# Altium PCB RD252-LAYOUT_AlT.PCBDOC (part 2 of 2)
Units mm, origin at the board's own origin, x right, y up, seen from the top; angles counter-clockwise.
Board outline 55 x 54 mm, 2 copper layers (TOP, BOTTOM), stack 0 mm thick; 81 components, 42 nets, 652 pads, 0 vias.
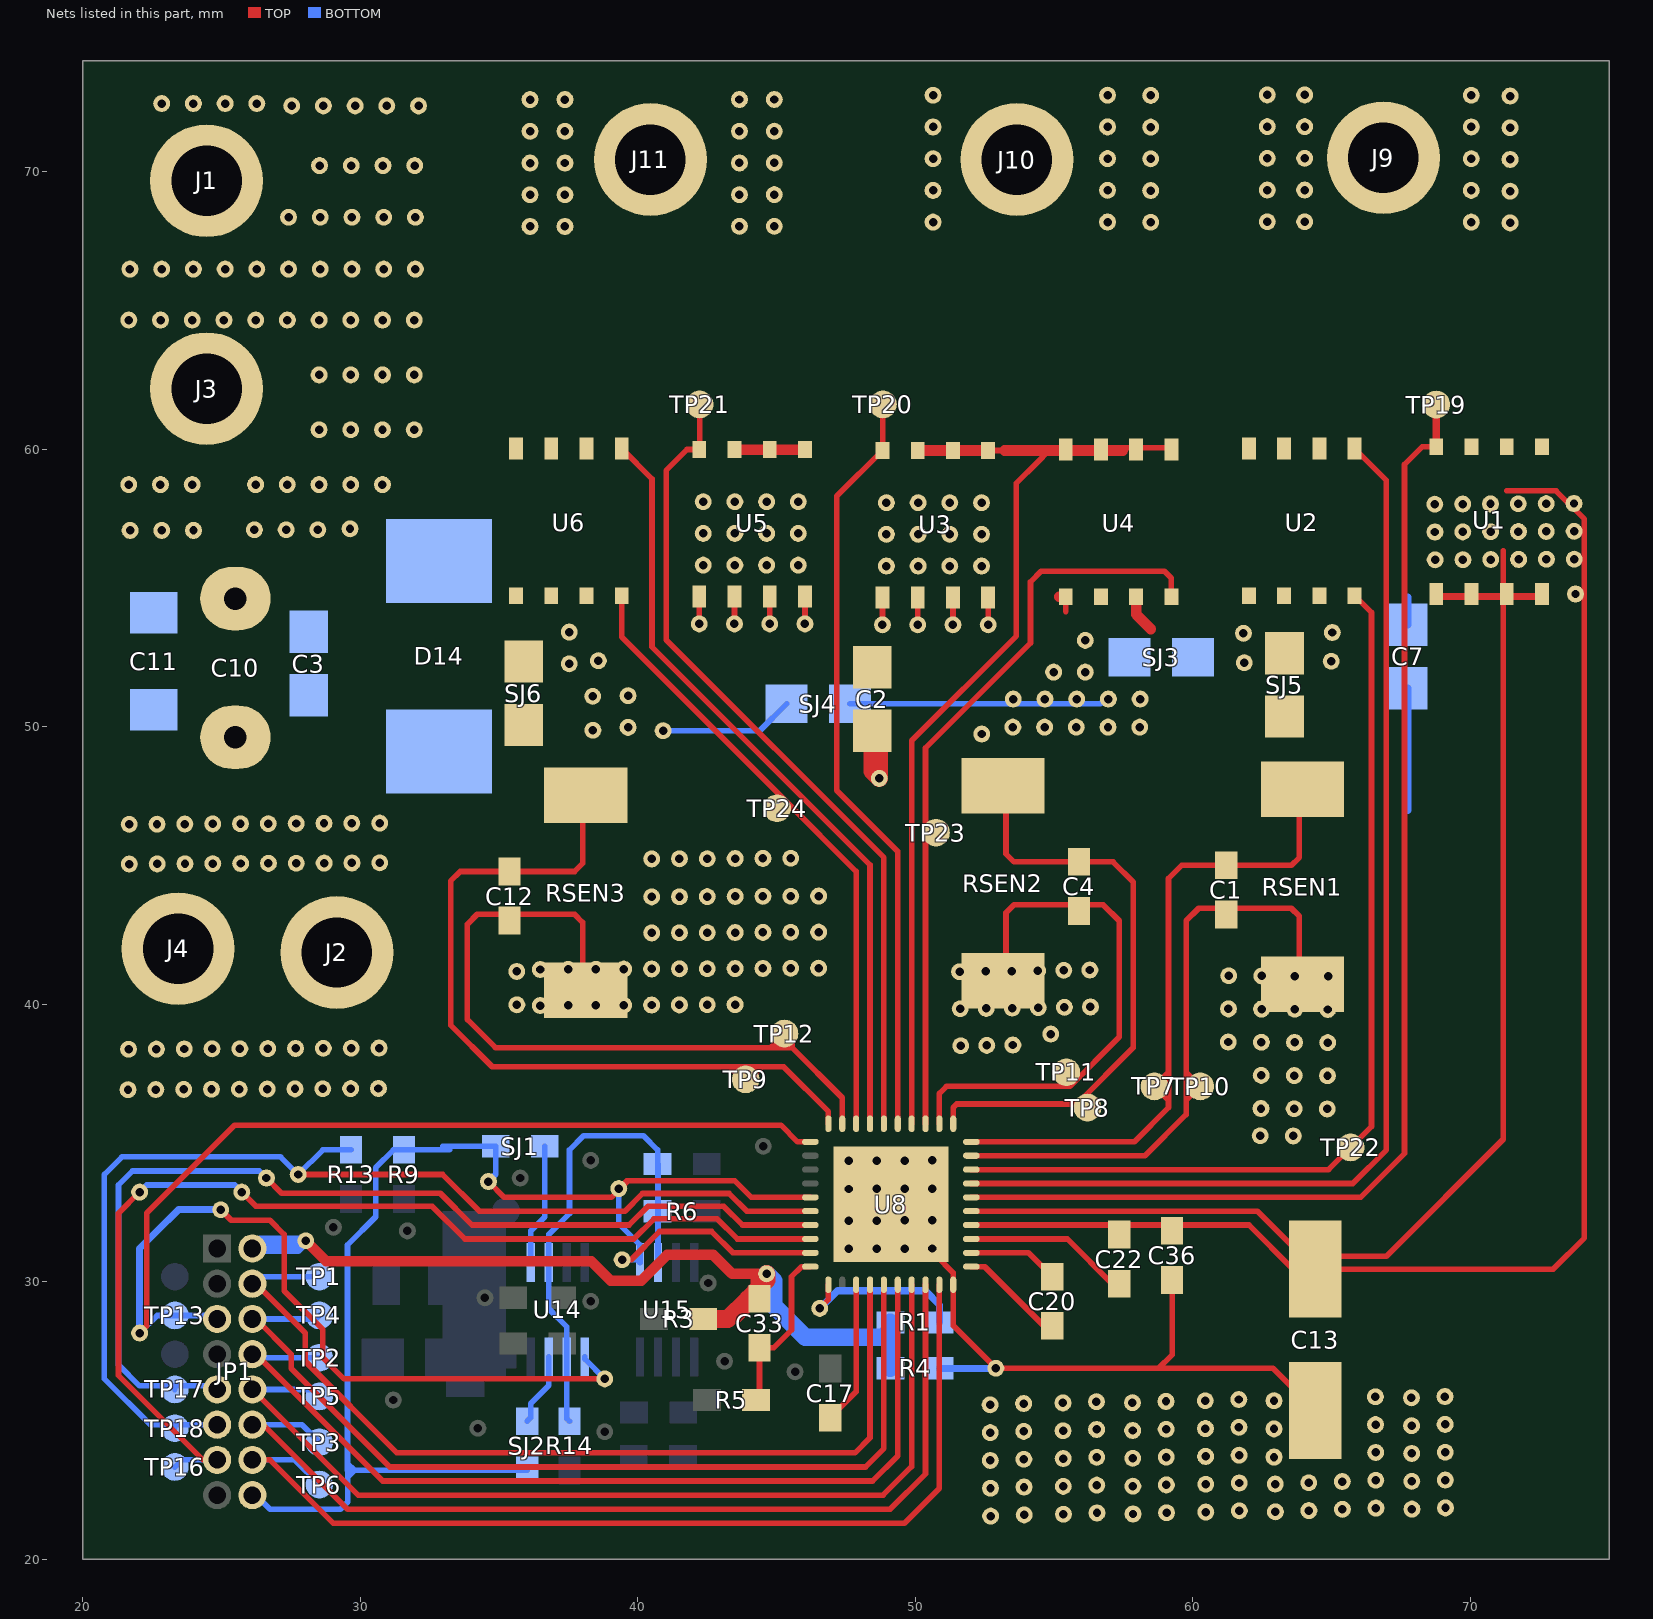
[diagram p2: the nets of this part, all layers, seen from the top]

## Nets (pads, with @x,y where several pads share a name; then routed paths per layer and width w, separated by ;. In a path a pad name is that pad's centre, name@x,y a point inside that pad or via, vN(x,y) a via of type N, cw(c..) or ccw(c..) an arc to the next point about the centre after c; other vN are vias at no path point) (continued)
AINB12: JP1.5 pad.@22.041,28.153 pad.@24.962,32.598 pad.@38.805,26.502 TP13.1 U8.21 U14.5 | length 58.8
  TOP w0.203: pad.@22.041,28.153 22.295,28.407 22.295,32.471 25.47,35.646 45.155,35.646 45.756,35.045 U8.21@46.216,35.045 ; pad.@24.962,32.598 25.343,32.217 26.74,32.217 27.248,31.709 27.248,29.677 28.645,28.28 28.645,27.264 29.407,26.502 pad.@38.805,26.502
  BOTTOM w0.203: pad.@22.041,28.153 22.676,28.788 TP13.1@23.311,28.788 24.708,28.788 JP1.5@24.835,28.661 ; U14.5@38.088,27.293 38.088,27.219 pad.@38.805,26.502
  BOTTOM w0.254: pad.@22.041,28.153 22.041,31.201 22.651,31.811 23.438,32.598 pad.@24.962,32.598
EMG: JP1.16 pad.@34.614,33.614 pad.@39.313,33.36 pad.@39.431,30.795 R9.1 SJ1.2 SJ2.2 U8.25 U8.29 U15.1 | length 53.7
  TOP w0.203: pad.@34.614,33.614 35.183,33.045 39.05,33.045 39.594,33.589 ; pad.@39.313,33.36 39.593,33.64 43.495,33.64 44.09,33.045 U8.25@46.216,33.045 ; pad.@39.431,30.795 39.761,30.795 40.777,31.811 42.657,31.811 43.423,31.045 U8.29@46.216,31.045
  BOTTOM w0.203: JP1.16@26.105,22.311 26.232,22.311 26.74,21.803 29.28,21.803 29.542,22.065 29.542,22.97 ; 29.534,23.208 29.534,23.454 ; 33.209,34.757 33.09,34.757 ; pad.@34.614,33.614 34.876,33.876 SJ1.2@34.876,34.884 32.963,34.884 33.09,34.757 ; SJ2.2@36.011,23.208 29.78,23.208 ; pad.@39.313,33.36 39.313,32.09 40.075,31.328 U15.1@40.075,30.693 39.973,30.795 pad.@39.431,30.795 ; 29.534,23.454 29.78,23.208 ; 29.534,23.454 29.534,31.328 30.55,32.344 30.55,34.122 31.185,34.757 R9.1@31.566,34.757 33.09,34.757 ; 29.542,22.97 29.78,23.208 ; 29.542,22.97 29.542,23.208 29.78,23.208
GHA: TP19.1 U1.4 U8.6 | length 44
  TOP w0.203: U8.6@52.016,33.045 66.046,33.045 67.631,34.63 67.631,59.458 68.266,60.093 U1.4@68.774,60.093
  TOP w0.254: U1.4@68.774,60.093 TP19.1@68.774,61.617
GHB: TP20.1 U3.4 U8.15 | length 27.5
  TOP w0.203: U3.4@48.814,59.961 47.163,58.31 47.163,47.717 49.366,45.514 U8.15@49.366,35.695 ; U3.4@48.829,59.976 TP20.1@48.829,61.621
GHC: TP21.1 U5.4 U8.16 | length 29.9
  TOP w0.203: U5.4@42.21,59.995 41.77,59.995 41.017,59.241 41.017,53.139 48.866,45.29 U8.16@48.866,35.695 ; U5.4@42.225,60.01 TP21.1@42.225,61.621
GLA: TP22.1 U2.4 U8.8 | length 34.5
  TOP w0.203: U8.8@52.016,34.045 64.89,34.045 TP22.1@65.687,34.842 66.44,35.595 66.44,54.121 U2.4@65.832,54.729
GLB: TP23.1 U4.4 U8.13 | length 27.1
  TOP w0.203: U8.13@50.366,35.695 50.366,46.187 50.366,49.239 54.148,53.021 54.148,55.228 54.529,55.609 58.974,55.609 59.228,55.356 U4.4@59.228,54.695
GLC: TP24.1 U6.4 U8.18 | length 22.5
  TOP w0.203: U6.4@39.417,54.729 39.417,53.243 45.306,47.354 47.866,44.794 U8.18@47.866,35.695
GND: C33.2 JP1.2 pad.@28.026,31.481 pad.@44.638,30.287 R1.2 R3.2 R4.1 | length 35.6
  TOP w0.203: 43.241,28.661 43.655,28.661 C33.2@44.384,29.39
  TOP w0.381: pad.@28.026,31.481 28.763,30.744 38.313,30.744 39.025,30.033 40.117,30.033 41.057,30.973 42.708,30.973 43.393,30.287 pad.@44.638,30.287
  TOP w0.635: R3.2@42.353,28.661 43.241,28.661 43.97,29.39 ; 43.97,29.39 C33.2@44.384,29.804 ; 43.97,29.39 C33.2@44.384,29.39 C33.2@44.384,29.804 ; C33.2@44.384,29.804 44.638,30.058 pad.@44.638,30.287 44.384,30.033 C33.2@44.384,29.804
  BOTTOM w0.381: JP1.2@26.105,31.201 27.747,31.201 pad.@28.026,31.481 26.385,31.481 JP1.2@26.105,31.201
  BOTTOM w0.635: pad.@44.638,30.287 44.892,30.033 44.892,29.144 46.035,28.001 48.846,28.001 R1.2@49.1,28.255 ; R4.1@49.1,26.887 R1.2@49.1,28.255 ; R1.2@49.1,28.534 R1.2@49.1,28.255
NetC22_1: C22.1 U8.3 | length 6
  TOP w0.203: U8.3@52.016,31.545 55.479,31.545 57.093,29.931 C22.1@57.347,29.931
NetR1_1: pad.@46.552,29.042 R1.1 U8.31 | length 6.4
  TOP w0.203: pad.@46.552,29.042 46.866,29.356 U8.31@46.866,29.895
  BOTTOM w0.254: pad.@46.552,29.042 47.187,29.677 50.362,29.677 50.87,29.169 R1.1@50.87,28.534
NetR5_2: C33.1 R5.2 U8.30 | length 6.1
  TOP w0.203: R5.2@44.258,25.74 44.384,25.866 C33.1@44.384,27.62 44.892,27.62 45.536,28.264 45.536,30.185 45.896,30.545 U8.30@46.216,30.545
NetR14_2: ?.1 R6.1 R14.2 U14.2 U14.6 U15.2 | length 18.1
  BOTTOM w0.203: R14.2@37.535,24.97 37.438,25.067 U14.6@37.438,27.293 37.438,28.377 36.788,29.027 U14.2@36.788,30.693 36.788,31.709 37.535,32.456 37.535,34.757 38.043,35.265 40.202,35.265 40.71,34.757 ?.1@40.71,34.249 40.725,34.234 U15.2@40.725,30.693
NetSJ4_2: pad.@37.526,52.274 pad.@37.526,53.417 pad.@38.37,51.102 pad.@38.378,49.878 pad.@38.576,52.385 pad.@39.645,49.982 pad.@39.645,51.125 pad.@40.908,49.863 SJ4.2 SJ6.2 U6.1 U6.2 U6.3 | length 4.9
  BOTTOM w0.203: pad.@40.908,49.863 44.391,49.863 SJ4.2@45.358,50.83
NetU2_1: pad.@61.824,53.373 pad.@61.852,52.313 pad.@64.987,52.365 pad.@65.028,53.402 SJ3.1 SJ5.2 U2.1 U2.2 U2.3
NetU8_1: C20.2 U8.1 | length 3.8
  TOP w0.203: U8.1@52.016,30.545 52.499,30.545 54.629,28.415 C20.2@54.934,28.415
NetU8_2: C20.1 U8.2 | length 3.3
  TOP w0.203: U8.2@52.016,31.045 54.074,31.045 C20.1@54.934,30.185
NetU8_33: C17.1 U8.33 | length 5.2
  TOP w0.203: C17.1@46.933,25.105 47.866,26.038 U8.33@47.866,29.895
NetU14_1: SJ1.1 U14.1 | length 4.4
  BOTTOM w0.203: U14.1@36.138,30.693 36.138,31.836 36.646,32.344 SJ1.1@36.646,34.884
NetU14_7: SJ2.1 U14.7 | length 2.6
  BOTTOM w0.203: SJ2.1@36.011,24.978 36.138,25.105 36.138,25.613 36.788,26.263 U14.7@36.788,27.293
PGND: C1.2 C2.2 C3.2 C4.2 C7.2 C10.2 C11.2 C12.2 C13.2 C36.2 D14.A J2.1 J4.1 pad.@21.67,45.057 pad.@21.623,36.924 pad.@21.643,38.381 pad.@21.665,46.489 pad.@22.626,36.929 pad.@22.646,38.386 pad.@22.668,46.494 pad.@22.673,45.062 pad.@23.629,36.934 pad.@23.649,38.391 pad.@23.671,46.499 pad.@23.676,45.067 pad.@24.632,36.939 pad.@24.652,38.396 pad.@24.674,46.503 pad.@24.679,45.071 pad.@25.635,36.943 pad.@25.655,38.4 pad.@25.677,46.508 pad.@25.682,45.076 pad.@26.68,46.513 pad.@26.638,36.948 pad.@26.658,38.405 pad.@26.685,45.081 pad.@27.641,36.953 pad.@27.661,38.41 pad.@27.683,46.518 pad.@27.688,45.086 pad.@28.644,36.958 pad.@28.664,38.415 pad.@28.686,46.523 pad.@28.691,45.091 pad.@29.646,36.963 pad.@29.667,38.42 pad.@29.689,46.527 pad.@29.694,45.095 pad.@30.67,38.425 pad.@30.649,36.968 pad.@30.692,46.532 pad.@30.697,45.1 pad.@35.633,41.186 pad.@35.638,39.984 pad.@36.482,39.957 pad.@36.482,41.256 pad.@37.484,39.961 pad.@37.485,41.261 pad.@38.487,39.966 pad.@38.488,41.265 pad.@39.49,39.971 pad.@39.491,41.27 pad.@40.493,39.976 pad.@40.494,41.275 pad.@40.495,42.574 pad.@40.495,45.241 pad.@40.496,43.873 pad.@41.496,39.981 pad.@41.497,41.28 pad.@41.498,42.579 pad.@41.498,45.246 pad.@41.499,43.878 pad.@42.5,41.285 pad.@42.499,39.985 pad.@42.501,42.584 pad.@42.501,45.251 pad.@42.502,43.883 pad.@43.502,39.99 pad.@43.503,41.289 pad.@43.504,42.589 pad.@43.504,45.256 pad.@43.505,43.888 pad.@44.506,41.294 pad.@44.507,42.593 pad.@44.507,45.26 pad.@44.508,43.893 pad.@45.51,42.598 pad.@45.51,45.265 pad.@45.509,41.299 pad.@45.511,43.897 pad.@46.512,41.304 pad.@46.513,42.603 pad.@46.514,43.902 pad.@47.607,31.187 pad.@47.607,32.203 pad.@47.607,33.346 pad.@47.607,34.362 pad.@48.61,31.191 pad.@48.61,32.207 pad.@48.61,33.35 pad.@48.61,34.366 pad.@48.702,48.143 pad.@49.613,31.196 pad.@49.613,32.212 pad.@49.613,33.355 pad.@49.613,34.371 pad.@50.616,31.201 pad.@50.616,32.217 pad.@50.616,33.36 pad.@50.616,34.376 pad.@51.593,41.174 pad.@51.615,39.841 pad.@51.636,38.509 pad.@52.532,41.187 pad.@52.554,39.854 pad.@52.575,38.521 pad.@52.693,25.567 pad.@52.698,24.564 pad.@52.703,23.561 pad.@52.708,22.558 pad.@52.712,21.555 pad.@52.902,26.883 pad.@53.92,21.6 pad.@53.472,41.2 pad.@53.493,39.867 pad.@53.515,38.534 pad.@53.901,25.612 pad.@53.906,24.609 pad.@53.911,23.606 pad.@53.916,22.603 pad.@54.88,38.93 pad.@54.411,41.212 pad.@54.433,39.88 pad.@55.35,41.225 pad.@55.319,25.636 pad.@55.323,24.633 pad.@55.328,23.63 pad.@55.333,22.627 pad.@55.338,21.624 pad.@55.372,39.892 pad.@56.29,41.238 pad.@56.311,39.905 pad.@56.526,25.681 pad.@56.531,24.678 pad.@56.536,23.675 pad.@56.541,22.672 pad.@56.546,21.669 pad.@57.83,24.641 pad.@57.825,25.644 pad.@57.835,23.638 pad.@57.839,22.635 pad.@57.844,21.632 pad.@59.033,25.689 pad.@59.038,24.686 pad.@59.043,23.683 pad.@59.047,22.68 pad.@59.052,21.677 pad.@60.45,25.713 pad.@60.46,23.707 pad.@60.47,21.701 pad.@60.455,24.71 pad.@60.465,22.704 pad.@61.277,38.642 pad.@61.284,39.837 pad.@61.291,41.032 pad.@61.658,25.758 pad.@61.663,24.755 pad.@61.668,23.752 pad.@61.673,22.749 pad.@61.677,21.746 pad.@62.427,35.265 pad.@62.457,36.245 pad.@62.464,37.44 pad.@62.471,38.635 pad.@62.479,39.83 pad.@62.486,41.024 pad.@62.926,23.683 pad.@62.926,24.699 pad.@62.926,25.715 pad.@62.971,22.712 pad.@62.976,21.709 pad.@63.622,35.258 pad.@63.651,36.238 pad.@63.659,37.433 pad.@63.666,38.627 pad.@63.673,39.822 pad.@63.681,41.017 pad.@64.179,22.757 pad.@64.184,21.754 pad.@64.846,36.231 pad.@64.853,37.425 pad.@64.861,38.62 pad.@64.868,39.815 pad.@64.876,41.01 pad.@65.387,22.802 pad.@65.392,21.799 pad.@66.6,21.844 pad.@66.58,25.856 pad.@66.59,23.85 pad.@66.585,24.853 pad.@66.595,22.847 pad.@67.879,25.819 pad.@67.884,24.816 pad.@67.889,23.813 pad.@67.894,22.81 pad.@67.898,21.807 pad.@69.087,25.864 pad.@69.092,24.861 pad.@69.097,23.858 pad.@69.101,22.855 pad.@69.106,21.852 R4.2 RSEN1.1 RSEN2.1 RSEN3.1 TP10.1 TP11.1 TP12.1 U8.9 U8.12 U8.19 U8.40 U8.41 | length 103.7
  TOP w0.203: C12.2@35.376,43.02 C12.2@35.151,43.245 ; RSEN3.1@38.006,41.019 38.006,42.956 37.717,43.245 C12.2@35.151,43.245 ; U8.41@47.366,34.603 pad.@47.607,34.362 ; U8.19@47.366,35.695 47.366,36.634 45.56,38.44 ; pad.@50.616,34.376 U8.41@50.866,34.626 ; pad.@50.743,30.947 51.366,30.324 U8.40@51.366,29.895 51.366,28.419 pad.@52.902,26.883 58.769,26.883 ; U8.12@50.866,35.695 50.866,36.789 51.12,37.043 55.569,37.043 57.347,38.821 57.347,43.012 56.768,43.591 C4.2@55.674,43.591 ; U8.9@52.016,34.545 58.278,34.545 59.76,36.027 59.76,36.535 ; RSEN2.1@53.269,40.722 53.269,41.2 53.269,43.266 ; pad.@53.269,41.365 53.269,43.302 53.558,43.591 C4.2@55.674,43.591 ; C4.2@55.899,43.366 C4.2@55.674,43.591 ; C36.2@59.252,30.066 59.252,27.366 58.769,26.883 ; C1.2@61.208,43.239 C1.2@60.983,43.464 ; pad.@63.838,41.238 63.838,43.175 63.549,43.464 C1.2@60.983,43.464 ; C13.2@64.416,25.355 62.888,26.883 58.769,26.883 ; C12.2@35.151,43.245 34.212,43.245 33.852,42.885 33.852,39.456 34.868,38.44 44.774,38.44 ; 44.774,38.44 TP12.1@45.282,38.948 45.56,38.67 45.56,38.44 ; 44.774,38.44 45.56,38.44 ; 59.76,36.535 TP10.1@60.268,37.043 59.76,37.551 ; 59.76,36.535 59.76,37.551 ; 59.76,37.551 59.76,43.012 60.212,43.464 C1.2@60.983,43.464
  TOP w0.635: C2.2@48.702,49.718 C2.2@48.702,49.607 ; C2.2@48.702,49.607 pad.@48.702,48.143 48.448,48.397 C2.2@48.448,49.861 C2.2@48.702,49.607
  BOTTOM w0.254: R4.2@50.874,26.883 pad.@52.902,26.883 ; 67.761,46.985 C7.2@67.761,51.394
SCLK: JP1.13 pad.@22.041,33.233 pad.@25.724,33.233 TP16.1 U8.28 | length 39.1
  TOP w0.203: pad.@22.041,33.233 21.279,32.471 21.279,26.629 24.327,23.581 JP1.13@24.835,23.581 ; pad.@25.724,33.233 26.232,32.725 32.582,32.725 33.762,31.545 39.851,31.545 40.574,32.268 42.86,32.268 43.583,31.545 U8.28@46.216,31.545
  BOTTOM w0.203: pad.@22.041,33.233 22.295,33.487 25.47,33.487 pad.@25.724,33.233 ; TP16.1@23.311,23.327 23.565,23.581 JP1.13@24.835,23.581
SDI: JP1.9 pad.@26.613,33.741 TP17.1 U8.27 | length 37.1
  TOP w0.203: pad.@26.613,33.741 27.161,33.193 32.876,33.193 34.024,32.045 39.685,32.045 40.365,32.725 43.089,32.725 43.769,32.045 U8.27@46.216,32.045
  BOTTOM w0.203: TP17.1@23.311,26.121 TP17.1@23.184,26.248 ; JP1.9@24.835,26.121 24.708,26.248 TP17.1@23.184,26.248 ; pad.@26.613,33.741 26.359,33.995 21.787,33.995 21.279,33.487 21.279,27.01 22.041,26.248 TP17.1@23.184,26.248
SDO: JP1.11 pad.@27.756,33.868 R13.1 TP18.1 U8.26 | length 41.6
  TOP w0.203: pad.@27.756,33.868 32.963,33.868 34.286,32.545 39.53,32.545 40.168,33.183 43.289,33.183 43.927,32.545 U8.26@46.216,32.545
  BOTTOM w0.203: TP18.1@23.311,24.724 TP18.1@23.184,24.851 ; JP1.11@24.835,24.851 TP18.1@23.184,24.851 ; R13.1@29.661,34.757 28.645,34.757 pad.@27.756,33.868 27.121,34.503 21.406,34.503 20.771,33.868 20.771,26.502 22.422,24.851 TP18.1@23.184,24.851
SHA: J9.1 pad.@62.684,68.205 pad.@62.684,69.348 pad.@62.684,70.491 pad.@62.684,71.634 pad.@62.684,72.777 pad.@64.03,68.206 pad.@64.03,69.349 pad.@64.03,70.492 pad.@64.03,71.635 pad.@64.03,72.778 pad.@70.037,68.194 pad.@70.037,69.337 pad.@70.037,70.48 pad.@70.037,71.623 pad.@70.037,72.766 pad.@71.434,68.165 pad.@71.434,69.308 pad.@71.434,70.451 pad.@71.434,71.594 pad.@71.434,72.737 U1.1 U1.2 U1.3 U2.5 U2.6 U2.7 U2.8 U8.7 | length 41.2
  TOP w0.203: U8.7@52.016,33.545 65.764,33.545 66.975,34.757 66.975,58.886 U2.5@65.832,60.029
SHB: J10.1 pad.@50.638,68.193 pad.@50.638,69.336 pad.@50.638,70.479 pad.@50.638,71.622 pad.@50.638,72.765 pad.@56.927,68.195 pad.@56.927,69.338 pad.@56.927,70.481 pad.@56.927,71.624 pad.@56.927,72.767 pad.@58.48,68.187 pad.@58.48,69.33 pad.@58.48,70.473 pad.@58.48,71.616 pad.@58.48,72.759 U3.1 U3.2 U3.3 U4.5 U4.6 U4.7 U4.8 U8.14 | length 38.1
  TOP w0.203: U8.14@49.866,35.695 49.866,49.501 53.64,53.275 53.64,58.784 54.378,59.522 54.817,59.961 54.91,60.054 U4.5@59.169,60.054 ; U3.1@52.624,59.961 53.225,59.961
  TOP w0.381: U3.3@50.084,59.961 U3.2@51.354,59.961 U3.1@52.624,59.961 ; 53.225,59.961 54.817,59.961 57.469,59.961
SHC: J11.1 pad.@36.114,68.036 pad.@36.114,69.179 pad.@36.114,70.322 pad.@36.114,71.465 pad.@36.114,72.608 pad.@37.371,68.037 pad.@37.371,69.18 pad.@37.371,70.323 pad.@37.371,71.466 pad.@37.371,72.609 pad.@43.66,68.04 pad.@43.66,69.183 pad.@43.66,70.326 pad.@43.66,71.469 pad.@43.66,72.612 pad.@44.918,68.04 pad.@44.918,69.183 pad.@44.918,70.326 pad.@44.918,71.469 pad.@44.918,72.612 U5.1 U5.2 U5.3 U6.5 U6.6 U6.7 U6.8 U8.17 | length 30.6
  TOP w0.203: U6.5@39.417,60.029 40.509,58.937 40.509,52.885 48.366,45.028 U8.17@48.366,35.695
  TOP w0.381: U5.3@43.48,59.995 U5.2@44.75,59.995 U5.1@46.02,59.995
SNA: C1.1 RSEN1.2 SJ5.1 TP7.1 U8.10 | length 24.8
  TOP w0.203: U8.10@52.016,35.045 57.889,35.045 59.125,36.281 59.125,36.535 ; RSEN1.2@63.951,47.747 63.838,47.634 63.838,45.298 63.549,45.009 C1.1@61.208,45.009 59.598,45.009 59.125,44.536 59.125,37.551 ; 59.125,36.535 59.125,37.551 ; 59.125,36.535 TP7.1@58.617,37.043 59.125,37.551
SNB: C4.1 pad.@52.394,49.743 pad.@53.514,49.991 pad.@53.528,51.004 pad.@54.657,49.991 pad.@54.671,51.004 pad.@54.983,51.975 pad.@55.8,49.991 pad.@55.814,51.004 pad.@56.126,51.975 pad.@56.126,53.118 pad.@56.943,49.991 pad.@56.957,51.004 pad.@58.1,51.004 pad.@58.086,49.991 RSEN2.2 SJ3.2 SJ4.1 TP8.1 U4.1 U4.2 U4.3 U8.11 | length 32.8
  TOP w0.203: U8.11@51.366,35.695 51.366,36.281 51.493,36.408 55.823,36.408 57.855,38.44 57.855,44.409 57.128,45.136 C4.1@55.899,45.136 53.558,45.136 53.269,45.425 53.269,47.691 53.161,47.799 53.156,47.799 RSEN2.2@53.156,47.874 ; 55.418,54.16 U4.1@55.418,54.695
  TOP w0.381: U4.1@55.179,54.695 U4.1@55.418,54.695 ; U4.3@57.958,54.695 57.958,54.052 58.481,53.529
  BOTTOM w0.203: SJ4.1@47.644,50.83 54.671,50.83 56.661,50.83 pad.@56.788,50.957
SNC: C12.1 RSEN3.2 SJ6.1 TP9.1 U8.20 | length 29.7
  TOP w0.203: RSEN3.2@38.119,47.528 38.006,47.415 38.006,45.079 37.717,44.79 C12.1@35.376,44.79 33.598,44.79 33.25,44.442 33.25,39.25 34.75,37.75 43.305,37.75 ; U8.20@46.866,35.695 46.866,36.134 45.25,37.75 44.465,37.75 ; 43.305,37.75 44.465,37.75 ; 43.305,37.75 43.821,37.233 43.885,37.17 44.465,37.75
U0: JP1.4 TP1.1 U8.34 | length 33.6
  TOP w0.203: JP1.4@26.105,29.931 26.232,29.931 28.01,28.153 28.01,27.137 31.312,23.835 47.822,23.835 48.366,24.379 U8.34@48.366,29.895
  BOTTOM w0.203: JP1.4@26.105,29.931 26.359,30.185 TP1.1@28.518,30.185
V0: JP1.8 TP2.1 U8.36 | length 34.2
  TOP w0.203: JP1.8@26.105,27.391 26.232,27.391 30.804,22.819 48.457,22.819 49.366,23.728 U8.36@49.366,29.895
  BOTTOM w0.203: JP1.8@26.105,27.391 26.232,27.264 TP2.1@28.518,27.264
VM: C2.1 C3.1 C7.1 C10.1 C11.1 C13.1 C22.2 C36.1 D14.C J1.1 J3.1 pad.@21.649,58.732 pad.@21.653,64.663 pad.@21.693,66.5 pad.@21.697,57.081 pad.@22.84,57.081 pad.@22.792,58.732 pad.@22.796,64.663 pad.@22.836,66.5 pad.@22.836,72.466 pad.@23.935,58.732 pad.@23.939,64.663 pad.@23.979,66.5 pad.@23.979,72.466 pad.@23.983,57.081 pad.@25.082,64.663 pad.@25.122,66.5 pad.@25.122,72.466 pad.@26.178,57.107 pad.@26.221,58.732 pad.@26.225,64.663 pad.@26.265,66.5 pad.@26.265,72.466 pad.@27.321,57.107 pad.@27.364,58.732 pad.@27.368,64.663 pad.@27.408,66.5 pad.@27.409,68.367 pad.@27.522,72.382 pad.@28.464,57.107 pad.@28.507,58.732 pad.@28.508,60.709 pad.@28.509,62.686 pad.@28.511,64.663 pad.@28.526,70.229 pad.@28.551,66.5 pad.@28.552,68.367 pad.@28.665,72.382 pad.@29.65,58.732 pad.@29.624,57.139 pad.@29.651,60.709 pad.@29.652,62.686 pad.@29.654,64.663 pad.@29.669,70.229 pad.@29.694,66.5 pad.@29.695,68.367 pad.@29.808,72.382 pad.@30.793,58.732 pad.@30.794,60.709 pad.@30.795,62.686 pad.@30.797,64.663 pad.@30.812,70.229 pad.@30.837,66.5 pad.@30.838,68.367 pad.@30.951,72.382 pad.@31.94,64.663 pad.@31.98,66.5 pad.@31.937,60.709 pad.@31.938,62.686 pad.@31.955,70.229 pad.@31.981,68.367 pad.@32.094,72.382 pad.@42.21,53.712 pad.@42.352,55.83 pad.@42.352,56.973 pad.@42.352,58.116 pad.@43.48,53.712 pad.@43.495,55.83 pad.@43.495,56.973 pad.@43.495,58.116 pad.@44.75,53.712 pad.@44.638,55.83 pad.@44.638,56.973 pad.@44.638,58.116 pad.@45.781,55.83 pad.@45.781,56.973 pad.@45.781,58.116 pad.@46.02,53.712 pad.@48.814,53.678 pad.@48.956,55.796 pad.@48.956,56.939 pad.@48.956,58.082 pad.@50.084,53.678 pad.@50.099,55.796 pad.@50.099,56.939 pad.@50.099,58.082 pad.@51.242,55.796 pad.@51.242,56.939 pad.@51.242,58.082 pad.@51.354,53.678 pad.@52.385,55.796 pad.@52.385,56.939 pad.@52.385,58.082 pad.@52.624,53.678 pad.@68.723,58.027 pad.@68.728,57.024 pad.@68.732,56.021 pad.@69.73,57.029 pad.@69.726,58.032 pad.@69.735,56.026 pad.@70.729,58.037 pad.@70.733,57.034 pad.@70.738,56.031 pad.@71.732,58.042 pad.@71.736,57.039 pad.@71.741,56.036 pad.@72.735,58.046 pad.@72.739,57.043 pad.@72.744,56.04 pad.@73.738,58.051 pad.@73.742,57.048 pad.@73.747,56.045 pad.@73.792,54.789 U1.5 U1.6 U1.7 U1.8 U3.5 U3.6 U3.7 U3.8 U5.5 U5.6 U5.7 U5.8 U8.4 U8.5 | length 110.6
  TOP w0.203: pad.@42.21,53.712 U5.5@42.21,54.695 U5.5@42.21,54.957 ; pad.@43.48,53.712 U5.6@43.48,54.695 U5.6@43.48,54.957 ; pad.@44.75,53.712 U5.7@44.75,54.695 U5.7@44.75,54.957 ; pad.@46.02,53.712 U5.8@46.02,54.695 U5.8@46.02,54.957 ; pad.@48.814,53.678 U3.5@48.814,54.661 U3.5@48.814,54.923 ; pad.@50.084,53.678 U3.6@50.084,54.661 U3.6@50.084,54.923 ; pad.@51.354,53.678 U3.7@51.354,54.923 ; U8.4@52.016,32.045 62.026,32.045 63.616,30.455 C13.1@64.416,30.455 ; U8.5@52.016,32.545 62.326,32.545 C13.1@64.416,30.455 ; pad.@52.624,53.678 U3.8@52.624,54.661 U3.8@52.624,54.923 ; C22.2@57.003,32.045 C22.2@57.347,31.701 ; 71.19,56.347 71.19,54.696 71.19,35.138 66.974,30.922 64.883,30.922 C13.1@64.416,30.455 ; 71.317,58.506 73.095,58.506 74.111,57.49 74.111,31.582 72.984,30.455 C13.1@64.416,30.455
  TOP w0.254: U1.5@68.904,54.696 71.19,54.696 U1.8@72.487,54.696
  BOTTOM w0.254: C7.1@67.761,53.68 67.761,54.678
W0: JP1.12 TP3.1 U8.38 | length 35.5
  TOP w0.203: JP1.12@26.105,24.851 26.486,24.851 29.534,21.803 49.092,21.803 50.366,23.077 U8.38@50.366,29.895
  BOTTOM w0.203: JP1.12@26.105,24.851 27.883,24.851 TP3.1@28.518,24.216
X0: JP1.6 TP4.1 U8.35 | length 33.9
  TOP w0.203: JP1.6@26.105,28.661 26.232,28.661 27.502,27.391 27.502,26.883 31.058,23.327 48.203,23.327 48.866,23.99 U8.35@48.866,29.895
  BOTTOM w0.203: JP1.6@26.105,28.661 28.391,28.661 TP4.1@28.518,28.788
Y0: JP1.10 TP5.1 U8.37 | length 34.8
  TOP w0.203: JP1.10@26.105,26.121 29.915,22.311 48.838,22.311 49.866,23.339 U8.37@49.866,29.895
  BOTTOM w0.203: JP1.10@26.105,26.121 28.264,26.121 TP5.1@28.518,25.867
Z0: JP1.14 TP6.1 U8.39 | length 36.3
  TOP w0.203: JP1.14@26.105,23.581 26.74,23.581 29.026,21.295 49.6,21.295 50.866,22.561 U8.39@50.866,29.895
  BOTTOM w0.203: JP1.14@26.105,23.581 27.629,23.581 TP6.1@28.518,22.692
pads on no net: U15.7

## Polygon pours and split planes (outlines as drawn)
PGND on TOP "TOP19" (solid, pour order 31): 90 vertices, not listed, extent 51.265,20.572 74.428,30.425
VM on TOP "TOP18" (solid, pour order 30): 56 vertices, not listed, extent 51.915,28.559 74.428,58.862
SNC on TOP "TOP17" (solid, pour order 29): 20 vertices, not listed, extent 33.018,46.623 39.495,50.814
VM on TOP "TOP16" (solid, pour order 28): 33 vertices, not listed, extent 41.624,51.546 46.654,58.735
VM on TOP "TOP15" (solid, pour order 27): 77 vertices, not listed, extent 47.593,51.419 53.258,58.735
SHC on TOP "TOP14" (solid, pour order 26): 22 vertices, not listed, extent 35.417,56.275 46.235,73.428
SHB on TOP "TOP13" (solid, pour order 25): 18 vertices, not listed, extent 49.894,56.148 59.434,73.428
SHA on TOP "TOP12" (solid, pour order 24): 24 vertices, not listed, extent 61.831,56.275 72.65,73.428
VM on TOP "TOP11" (solid, pour order 23): 85 vertices, not listed, extent 20.572,53.578 33.573,73.428
SHC on TOP "TOP10" (solid, pour order 22): 22 vertices, not listed, extent 35.417,56.275 46.235,73.428
PGND on TOP "TOP9" (solid, pour order 21): 55 vertices, not listed, extent 20.572,36.027 32.074,51.775
PGND on TOP "TOP8" (solid, pour order 20): 104 vertices, not listed, extent 35.122,39.075 47.314,45.806
SNB on TOP "TOP7" (solid, pour order 19): 61 vertices, not listed, extent 50.925,47.004 58.672,54.886
SNA on TOP "TOP6" (solid, pour order 18): 59.497,47.004 cw(c59.497,47.194) 59.307,47.194 59.307,50.75 cw(c59.497,50.75) 59.497,50.941 65.72,50.941 cw(c65.72,50.75) 65.911,50.75 65.911,47.194 cw(c65.72,47.194) 65.72,47.004
NetU2_1 on TOP "TOP5" (solid, pour order 17): 49 vertices, not listed, extent 59.197,51.327 65.895,54.878
SHC on TOP "TOP4" (solid, pour order 16): 22 vertices, not listed, extent 35.417,56.275 46.235,73.428
NetSJ4_2 on TOP "TOP3" (solid, pour order 15): 118 vertices, not listed, extent 32.734,49.387 41.955,55.306
PGND on TOP "TOP2" (solid, pour order 14): 74 vertices, not listed, extent 60.522,34.757 65.983,41.742
PGND on TOP "TOP1" (solid, pour order 13): 42 vertices, not listed, extent 50.87,37.551 56.863,41.869
AGND on BOTTOM "BOTTOM30" (solid, pour order 12): 197 vertices, not listed, extent 20.707,20.596 47.81,31.996
PGND on BOTTOM "BOTTOM29" (solid, pour order 11): 68 vertices, not listed, extent 44.569,20.572 74.428,38.288
PGND on BOTTOM "BOTTOM28" (solid, pour order 10): 51 vertices, not listed, extent 20.572,35.798 74.428,52.131
VM on BOTTOM "BOTTOM27" (solid, pour order 9): 143 vertices, not listed, extent 20.572,52.689 74.34,73.34
AGND on BOTTOM "BOTTOM26" (solid, pour order 8): 31 vertices, not listed, extent 41.718,29.652 43.478,34.859
NetU2_1 on BOTTOM "BOTTOM25" (solid, pour order 7): 59.37,51.576 cw(c59.37,51.766) 59.18,51.766 59.18,53.798 cw(c59.37,53.798) 59.37,53.989 65.72,53.989 cw(c65.72,53.798) 65.911,53.798 65.911,51.766 cw(c65.72,51.766) 65.72,51.576
SNB on BOTTOM "BOTTOM24" (solid, pour order 6): 18 vertices, not listed, extent 46.988,49.417 58.672,53.989
NetSJ4_2 on BOTTOM "BOTTOM23" (solid, pour order 5): 56 vertices, not listed, extent 36.925,49.133 46.146,54.036
SHA on BOTTOM "BOTTOM22" (solid, pour order 4): 19 vertices, not listed, extent 61.792,67.269 74.365,73.365
SHB on BOTTOM "BOTTOM21" (solid, pour order 3): 21 vertices, not listed, extent 49.854,67.142 59.506,73.428
SHC on BOTTOM "BOTTOM20" (solid, pour order 2): 19 vertices, not listed, extent 35.376,67.269 46.171,73.365
no net on Top Solder "TOPSOLDER41" (solid, pour order 0): 61 vertices, not listed, extent 60.776,35.011 65.856,41.615
no net on Top Solder "TOPSOLDER40" (solid, pour order 0): 38 vertices, not listed, extent 50.997,37.805 56.585,41.742
no net on Top Solder "TOPSOLDER39" (solid, pour order 0): 65 vertices, not listed, extent 35.249,39.202 46.933,45.552
no net on Top Solder "TOPSOLDER38" (solid, pour order 0): 59.506,50.632 cw(c59.633,50.632) 59.633,50.759 65.602,50.759 cw(c65.602,50.632) 65.729,50.632 65.729,47.457 cw(c65.602,47.457) 65.602,47.33 59.76,47.33 cw(c59.76,47.457) 59.696,47.347 cw(c59.633,47.457) 59.506,47.457
no net on Top Solder "TOPSOLDER37" (solid, pour order 0): 70 vertices, not listed, extent 59.379,51.394 65.729,54.696
no net on Top Solder "TOPSOLDER36" (solid, pour order 0): 59 vertices, not listed, extent 51.124,47.203 58.49,54.823
no net on Top Solder "TOPSOLDER35" (solid, pour order 0): 33.344,46.695 cw(c33.344,46.822) 33.217,46.822 33.217,50.505 cw(c33.344,50.505) 33.344,50.632 37.027,50.632 cw(c37.027,50.505) 37.154,50.505 37.154,46.822 cw(c37.027,46.822) 37.027,46.695
no net on Top Solder "TOPSOLDER34" (solid, pour order 0): 38 vertices, not listed, extent 32.836,49.616 41.726,55.204
no net on Top Solder "TOPSOLDER33" (solid, pour order 0): 28 vertices, not listed, extent 61.919,59.522 72.46,73.238
no net on Top Solder "TOPSOLDER32" (solid, pour order 0): 50.235,59.903 cw(c50.235,60.03) 50.108,60.03 50.108,73.111 cw(c50.235,73.111) 50.235,73.238 59.125,73.238 cw(c59.125,73.111) 59.252,73.111 59.252,60.03 cw(c59.125,60.03) 59.125,59.903
no net on Top Solder "TOPSOLDER31" (solid, pour order 0): 30 vertices, not listed, extent 35.63,59.649 46.044,73.238

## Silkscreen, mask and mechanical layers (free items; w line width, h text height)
Top Overlay:
  drawing of 1101 lines, arcs and shapes, not listed
  text "RD252" at 71.018,31.407 h1.3 r90
  text "Inverter for Cordless Power Tool" at 73.736,23.139 h0.9 r90
Bottom Overlay:
  drawing of 790 lines, arcs and shapes, not listed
